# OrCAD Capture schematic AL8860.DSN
size Custom; title: AL8860, 40V 1.5A BUCK LED DRIVER; rev: 1.2; note: DS39014 Rev. 5 - 2
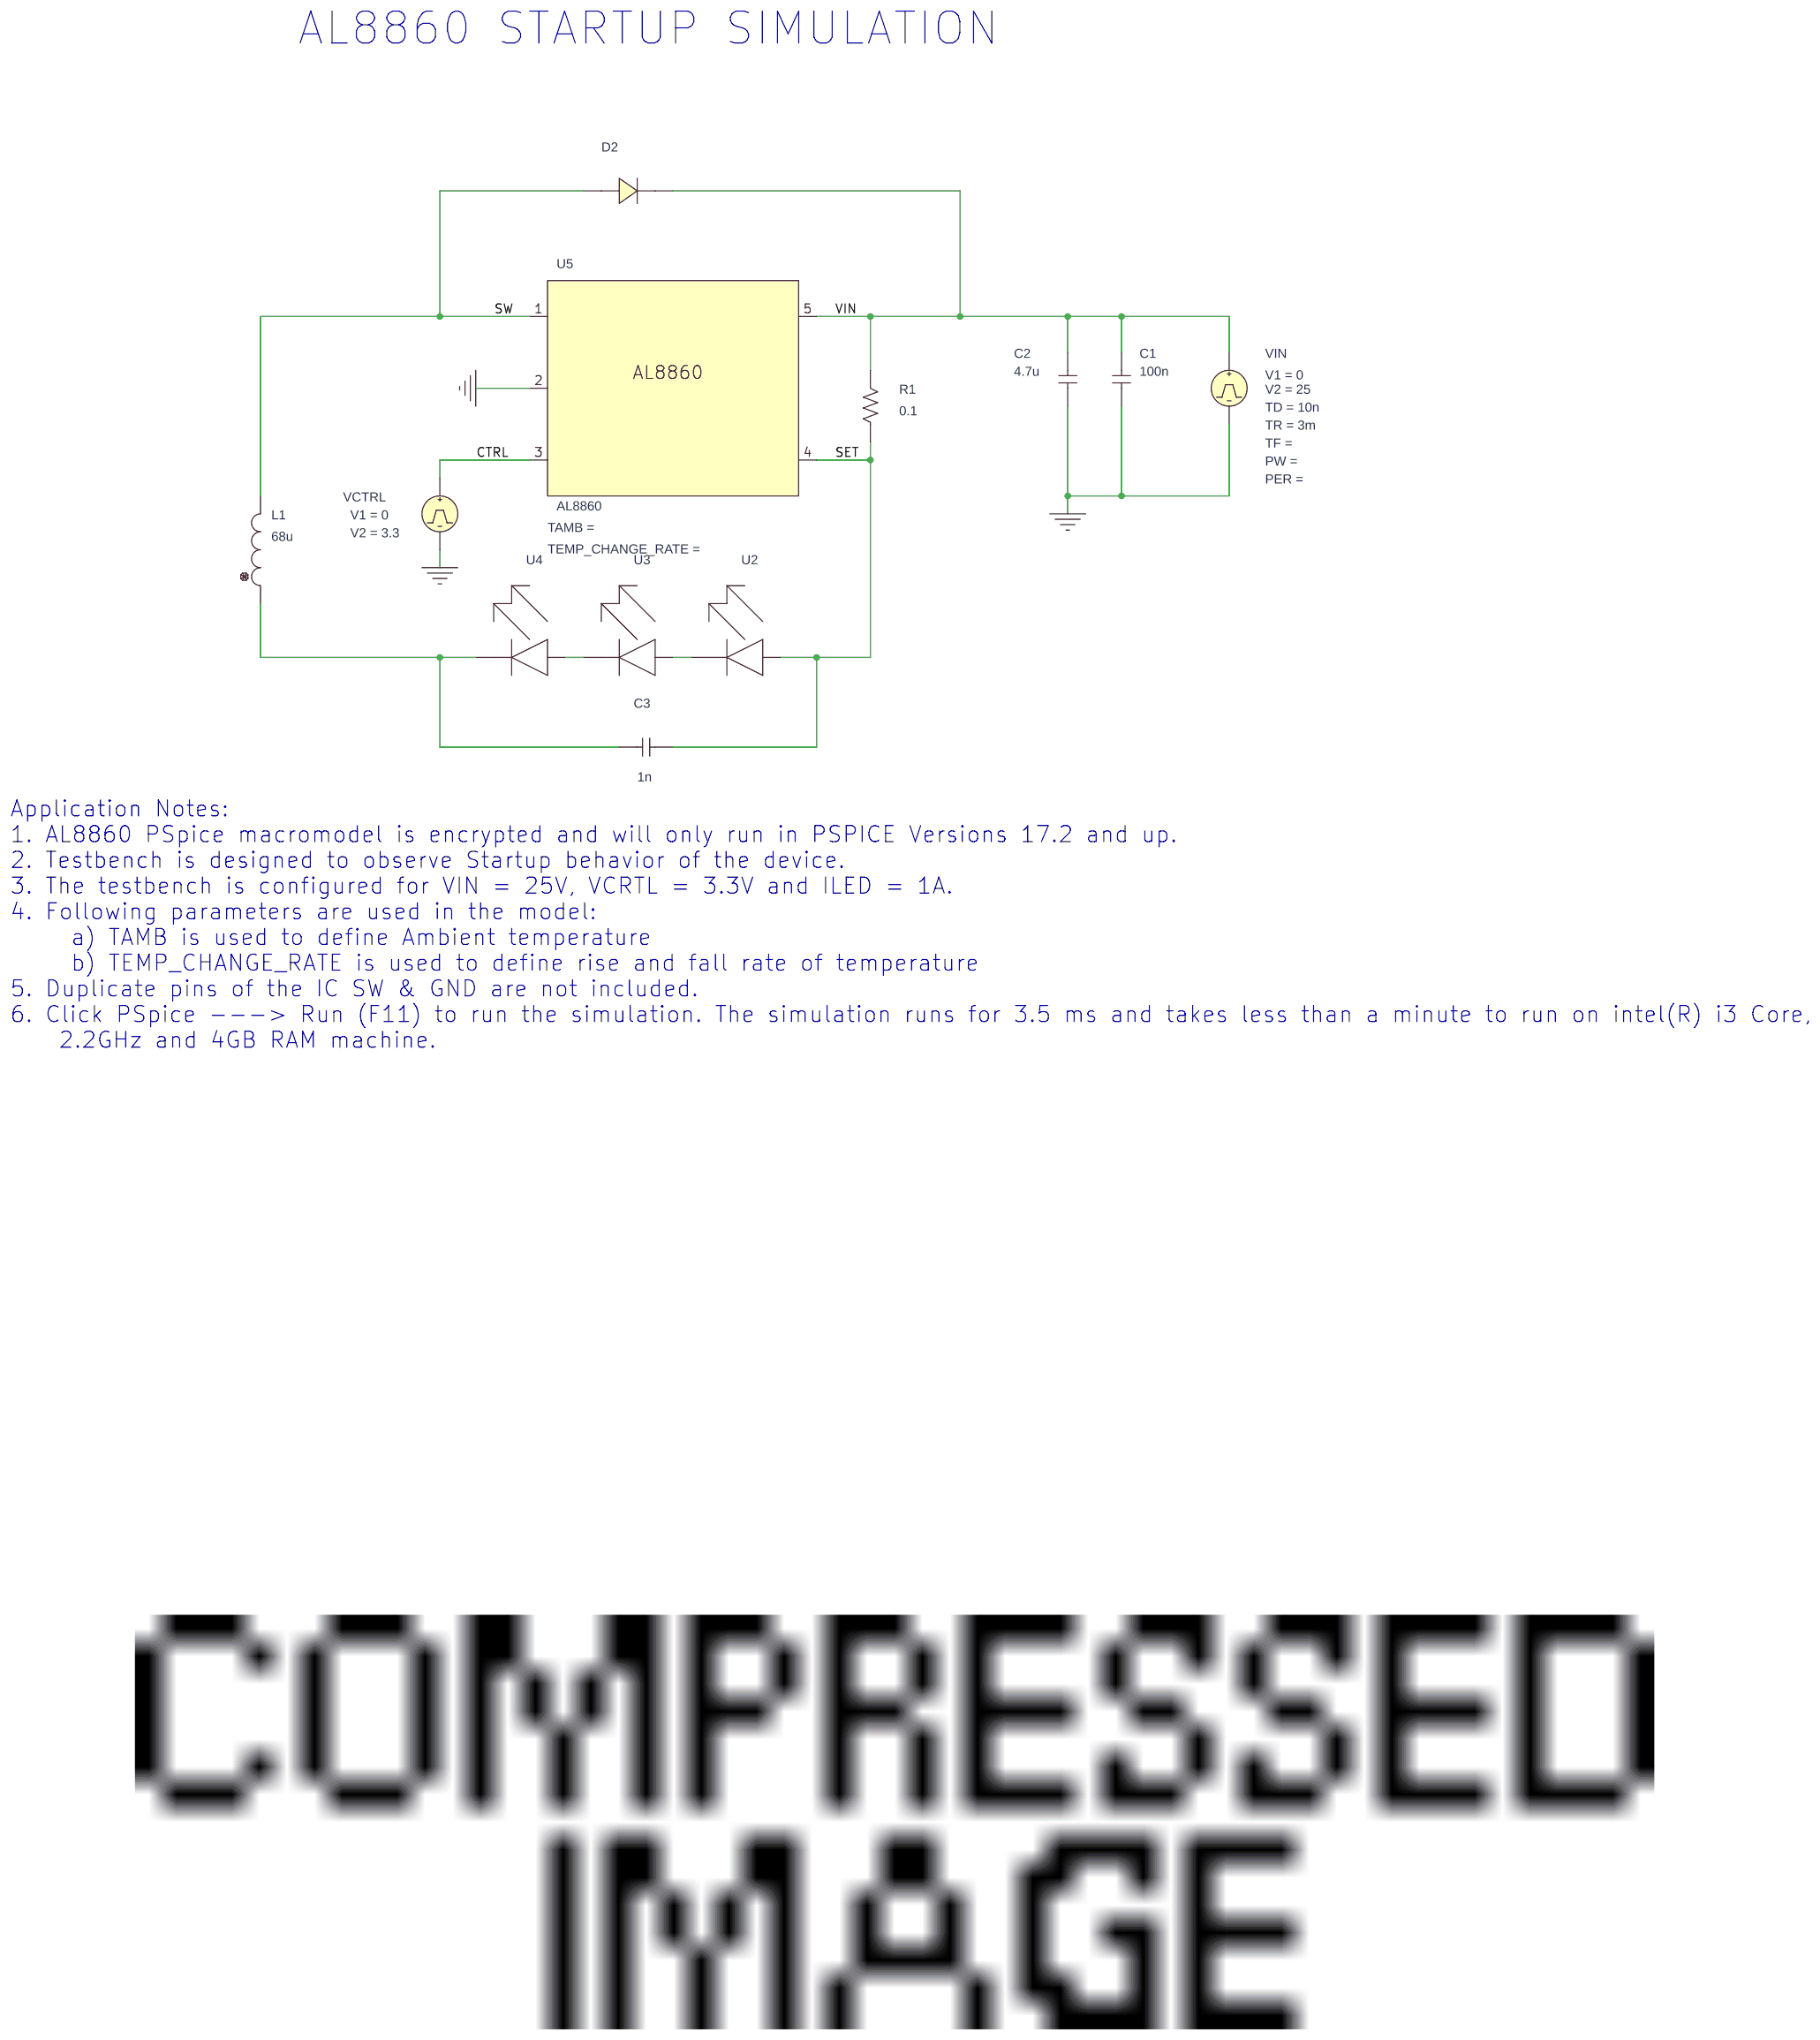
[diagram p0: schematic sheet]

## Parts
C1  100n  [RAD/CK05]
C2  4.7u  [RAD/CK05]
C3  1n  [RAD/CK05]
D2  B240A
L1  68u  [DISC/.350x.175/LS.200x.100/.034]
R1  0.1  [AX/RC05]
U2  _D2_mod
U3  _D2_mod
U4  _D2_mod
U5  AL8860
VCTRL  VPULSE
VIN  VPULSE

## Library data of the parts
C1-C3 = C
D2 = B240A
L1 = L: IC: 0
R1 = R
U2-U4 = LEDR
U5 = AL8860
VCTRL = VPULSE: V1: 0; V2: 3.3
VIN = VPULSE: TD: 10n; TR: 3m; V1: 0; V2: 25

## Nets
VIN: C1.2 C2.2 D2.1(C) R1.2 U5.5(VIN) VIN.1(+)
0: C1.1 C2.1 U5.2(GND) VCTRL.2(-) VIN.2(-)
CTRL: U5.3(CTRL) VCTRL.1(+)
SET: C3.2 R1.1 U2.1(A) U5.4(SET)
SW: D2.2(A) L1.2 U5.1(SW)
N21828: C3.1 L1.1 U4.2(C)
N22816: U2.2(C) U3.1(A)
N22866: U3.2(C) U4.1(A)

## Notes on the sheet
- AL8860 STARTUP SIMULATION
- Application Notes:
  1. AL8860 PSpice macromodel is encrypted and will only run in PSPICE Versions 17.2 and up.
  2. Testbench is designed to observe Startup behavior of the device.
  3. The testbench is configured for VIN = 25V, VCRTL = 3.3V and ILED = 1A.
  4. Following parameters are used in the model:
       a) TAMB is used to define Ambient temperature
       b) TEMP_CHANGE_RATE is used to define rise and fall rate of temperature
  5. Duplicate pins of the IC SW & GND are not included.
  6. Click PSpice ---> Run (F11) to run the simulation. The simulation runs for 3.5 ms and takes less than a minute to run on intel(R) i3 Core,
      2.2GHz and 4GB RAM machine.
